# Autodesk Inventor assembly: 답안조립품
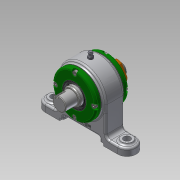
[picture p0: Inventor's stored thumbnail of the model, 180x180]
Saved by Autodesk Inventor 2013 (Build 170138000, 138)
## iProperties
Created: 2019-05
Part Number: 답안조립품
Document SubType Name: Assembly
Designer: Administrator
Author: Administrator
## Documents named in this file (13)
- C:\Users\Administrator\Desktop\490504V1048\답안조립품.iam
- C:\Users\Administrator\Desktop\490504V1048\본체.ipt
- C:\Users\Administrator\Desktop\490504V1048\개스킷.ipt
- C:\Users\Administrator\Desktop\490504V1048\그리스니플 M6.ipt
- 그리스니플  M6.ipt
- C:\Users\Administrator\Desktop\490504V1048\그리스니플개스킷.ipt
- C:\Users\Administrator\Desktop\490504V1048\베어링너트.ipt
- C:\Users\Administrator\Desktop\490504V1048\볼트 M4.ipt
- C:\Users\Administrator\Desktop\490504V1048\앵귤러 볼 베어링 7205.ipt
- C:\Users\Administrator\Desktop\490504V1048\오일 실 28 40 5 B.ipt
- C:\Users\Administrator\Desktop\490504V1048\축.ipt
- C:\Users\Administrator\Desktop\490504V1048\칼라.ipt
- C:\Users\Administrator\Desktop\490504V1048\커버.ipt
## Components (4 placed, 3 different names)
1. 개스킷:1
2. 그리스니플  M6:1
3. 그리스니플개스킷:1
4. 개스킷:2
